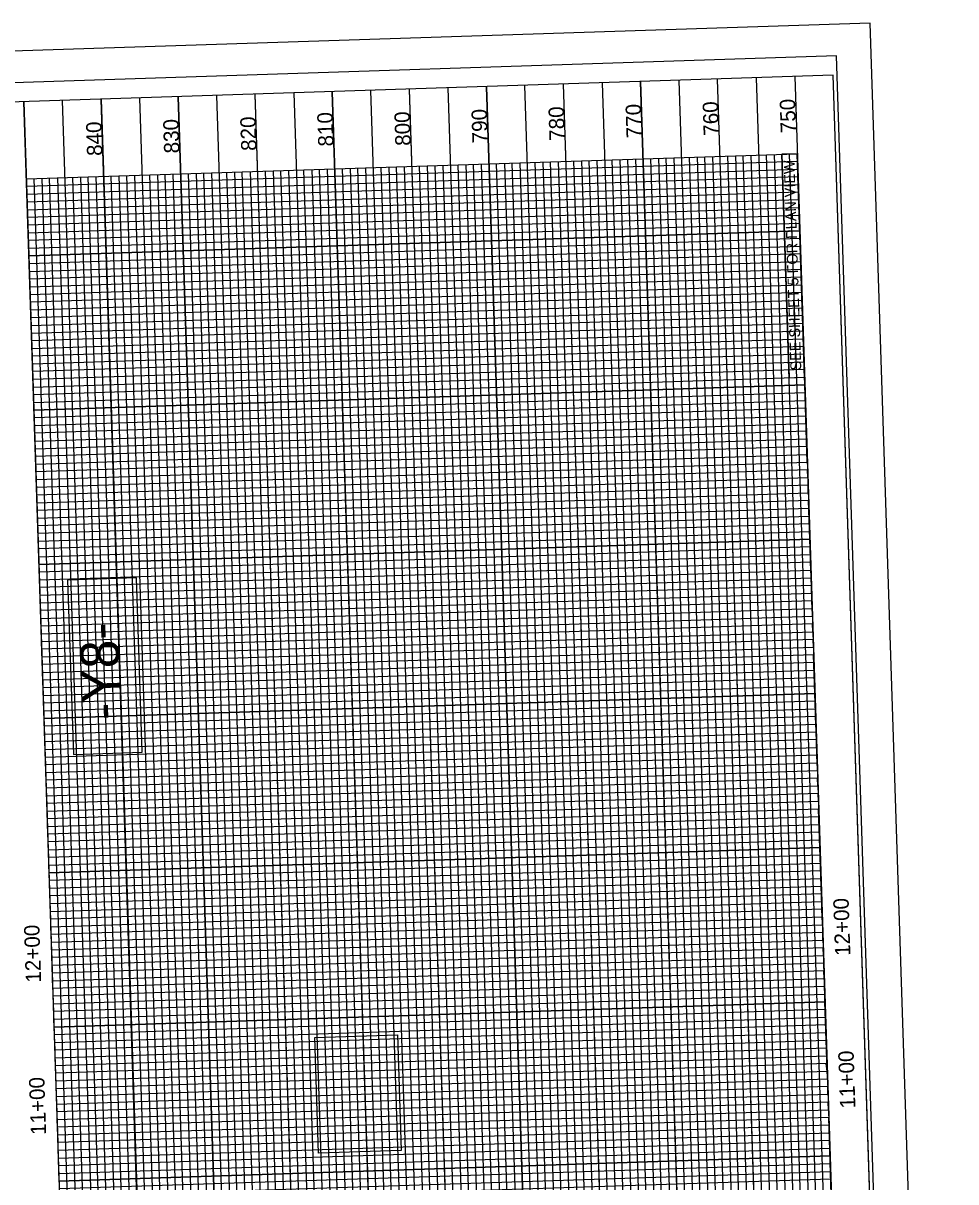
# Model space of a CAD drawing. Extents: x 1627314 to 1628469, y 762309 to 764247.
# Drawn here: x 1627864 to 1628469, y 763293 to 764044 of the extents above; entities that cross this region are included whole.
import ezdxf

# ---------------------------------------------------------------- set-up
doc = ezdxf.new("R2010")
doc.units = 0
for name, color, linetype in [('Exist Vertical Profile Horizontal Axis Label Major', 7, 'Continuous'), ('Exist Vertical Profile Vertical Axis Label', 7, 'Continuous'), ('Prop DSN Text', 7, 'Continuous'), ('Prop Grid Mask', 7, 'Continuous'), ('Sheet Data Field CELL', 7, 'Continuous'), ('Sheet DOT Grid CELL', 7, 'Continuous'), ('Sheet Layout Profile Border Port 2', 7, 'Continuous'), ('Sheet Plot Border Inside CELL', 7, 'Continuous'), ('Sheet Plot Border Outside CELL', 7, 'Continuous'), ('Sheet Profile CELL', 7, 'Continuous'), ('Sheet Profile Grid Major CELL', 7, 'Continuous'), ('Sheet Profile Grid Middle CELL', 7, 'Continuous'), ('Sheet Profile Grid Minor CELL', 7, 'Continuous')]:
    doc.layers.add(name, color=color, linetype=linetype)

msp = doc.modelspace()

# ---------------------------------------------------------------- linework, layer by layer
at = {"layer": 'Prop Grid Mask'}
for points in [[(1628356.37, 763959.45), (1628361.12, 763814.53), (1628371.11, 763814.85), (1628366.37, 763959.78)], [(1627941.73, 763571.76), (1627938.03, 763684.79), (1627893.31, 763683.33), (1627897.01, 763570.3)], [(1628055.96, 763312.01), (1628053.51, 763386.86), (1628107.11, 763388.61), (1628109.56, 763313.76)]]:
    msp.add_lwpolyline(points, close=True, dxfattribs=at)
at = {"layer": 'Sheet DOT Grid CELL'}
for p, q in [((1628313.83, 762507.28), (1628264.79, 764006.37)), ((1628363.8, 762508.92), (1628314.77, 764008)), ((1628063.96, 762499.11), (1628014.93, 763998.19)), ((1628113.93, 762500.74), (1628064.9, 763999.83)), ((1628163.91, 762502.38), (1628114.87, 764001.46)), ((1628213.88, 762504.01), (1628164.85, 764003.1)), ((1628263.85, 762505.65), (1628214.82, 764004.73)), ((1627914.04, 762494.2), (1627865.01, 763993.29)), ((1627964.01, 762495.84), (1627914.98, 763994.92)), ((1628013.99, 762497.47), (1627964.95, 763996.56)), ((1627866.64, 763943.43), (1628366.37, 763959.78)), ((1627868.27, 763893.46), (1628368, 763909.8)), ((1627869.91, 763843.48), (1628369.64, 763859.83)), ((1627871.54, 763793.51), (1628371.27, 763809.86)), ((1627873.18, 763743.54), (1628372.91, 763759.88)), ((1627874.81, 763693.56), (1628374.54, 763709.91)), ((1627876.44, 763643.59), (1628376.18, 763659.94)), ((1627878.08, 763593.62), (1628377.81, 763609.96)), ((1627879.71, 763543.64), (1628379.45, 763559.99)), ((1627881.35, 763493.67), (1628381.08, 763510.02)), ((1627882.98, 763443.7), (1628382.72, 763460.04)), ((1627884.62, 763393.72), (1628384.35, 763410.07)), ((1627886.25, 763343.75), (1628385.99, 763360.1)), ((1627887.89, 763293.78), (1628387.62, 763310.12))]:
    msp.add_line(p, q, dxfattribs=at)
at = {"layer": 'Sheet Layout Profile Border Port 2'}
msp.add_lwpolyline([(1627912.41, 762544.18), (1627866.64, 763943.43), (1628366.37, 763959.78), (1628412.14, 762560.52)], close=True, dxfattribs=at)
at = {"layer": 'Sheet Plot Border Inside CELL'}
msp.add_lwpolyline([(1628446.34, 762357.53), (1628391.86, 764023.14), (1627337.33, 763988.65), (1627391.81, 762323.04)], close=True, dxfattribs=at)
at = {"layer": 'Sheet Plot Border Outside CELL'}
msp.add_lwpolyline([(1628469.21, 762345.27), (1628413.63, 764044.37), (1627314.22, 764008.4), (1627369.79, 762309.31)], close=True, dxfattribs=at)
at = {"layer": 'Sheet Profile CELL'}
for p, q in [((1628364.74, 764009.75), (1628413.77, 762510.55)), ((1628438.76, 762511.37), (1628389.72, 764010.57)), ((1627914.04, 762494.2), (1627865, 763993.4))]:
    msp.add_line(p, q, dxfattribs=at)
msp.add_lwpolyline([(1627340.28, 763976.24), (1627389.32, 762477.04), (1628438.76, 762511.37), (1628389.72, 764010.57)], close=True, dxfattribs=at)
at = {"layer": 'Sheet Profile Grid Major CELL'}
for p, q in [((1627868.27, 763893.46), (1627866.64, 763943.43)), ((1628368, 763909.8), (1628368, 763909.8)), ((1627871.54, 763793.51), (1627869.91, 763843.48)), ((1627874.81, 763693.56), (1627873.18, 763743.54)), ((1627878.08, 763593.62), (1627876.44, 763643.59)), ((1627881.35, 763493.67), (1627879.71, 763543.64)), ((1627884.62, 763393.72), (1627882.98, 763443.7)), ((1627887.89, 763293.78), (1627886.25, 763343.75))]:
    msp.add_line(p, q, dxfattribs=at)
for points in [[(1628264.79, 764006.48), (1628313.83, 762507.28), (1628313.83, 762507.28), (1628363.8, 762508.92), (1628314.76, 764008.11)], [(1628364.74, 764009.75), (1628413.77, 762510.55)], [(1627964.95, 763996.67), (1628013.99, 762497.47), (1628063.96, 762499.11), (1628014.92, 763998.31)], [(1628064.9, 763999.94), (1628113.93, 762500.74), (1628163.91, 762502.38), (1628114.87, 764001.58)], [(1628164.84, 764003.21), (1628213.88, 762504.01), (1628263.85, 762505.65), (1628214.82, 764004.85)], [(1627914.98, 763995.04), (1627964.01, 762495.84)], [(1628389.25, 763260.15), (1628387.62, 763310.12), (1627887.89, 763293.78), (1627886.25, 763343.75), (1628385.99, 763360.1), (1628384.35, 763410.07), (1627884.62, 763393.72), (1627882.98, 763443.7), (1628382.72, 763460.04), (1628381.08, 763510.02), (1627881.35, 763493.67), (1627879.71, 763543.64), (1628379.45, 763559.99), (1628377.81, 763609.96), (1627878.08, 763593.62), (1627876.44, 763643.59), (1628376.18, 763659.94), (1628374.54, 763709.91), (1627874.81, 763693.56), (1627873.18, 763743.54), (1628372.91, 763759.88), (1628371.27, 763809.86), (1627871.54, 763793.51), (1627869.91, 763843.48), (1628369.64, 763859.83), (1628368, 763909.8), (1628368, 763909.8), (1627868.27, 763893.46), (1627866.64, 763943.43), (1628366.37, 763959.78)]]:
    msp.add_lwpolyline(points, dxfattribs=at)
at = {"layer": 'Sheet Profile Grid Middle CELL'}
for points in [[(1628239.8, 764005.66), (1628288.84, 762506.46), (1628338.81, 762508.1), (1628289.78, 764007.3)], [(1628339.75, 764008.93), (1628388.79, 762509.73)], [(1627939.96, 763995.85), (1627989, 762496.66), (1628038.97, 762498.29), (1627989.94, 763997.49)], [(1628039.91, 763999.12), (1628088.95, 762499.93), (1628138.92, 762501.56), (1628089.88, 764000.76)], [(1628139.86, 764002.39), (1628188.89, 762503.2), (1628238.87, 762504.83), (1628189.83, 764004.03)], [(1627939.03, 762495.02), (1627889.99, 763994.22)], [(1628388.44, 763285.14), (1628386.8, 763335.11), (1627887.07, 763318.76), (1627885.44, 763368.74), (1628385.17, 763385.08), (1628383.53, 763435.06), (1627883.8, 763418.71), (1627882.17, 763468.68), (1628381.9, 763485.03), (1628380.26, 763535), (1627880.53, 763518.66), (1627878.9, 763568.63), (1628378.63, 763584.98), (1628376.99, 763634.95), (1627877.26, 763618.6), (1627875.63, 763668.58), (1628375.36, 763684.92), (1628373.73, 763734.9), (1627873.99, 763718.55), (1627872.36, 763768.52), (1628372.09, 763784.87), (1628370.46, 763834.84), (1627870.72, 763818.5), (1627869.09, 763868.47), (1628368.82, 763884.82), (1628367.19, 763934.79), (1627867.45, 763918.44)]]:
    msp.add_lwpolyline(points, dxfattribs=at)
at = {"layer": 'Sheet Profile Grid Minor CELL'}
for p, q in [((1628192.26, 762553.33), (1628146.49, 763952.58)), ((1628151.48, 763952.75), (1628197.25, 762553.5)), ((1628202.25, 762553.66), (1628156.48, 763952.91)), ((1628161.48, 763953.07), (1628207.25, 762553.82)), ((1628217.24, 762554.15), (1628171.47, 763953.4)), ((1628176.47, 763953.56), (1628222.24, 762554.31)), ((1628227.24, 762554.48), (1628181.47, 763953.73)), ((1628186.47, 763953.89), (1628232.24, 762554.64)), ((1628242.23, 762554.97), (1628196.46, 763954.22)), ((1628201.46, 763954.38), (1628247.23, 762555.13)), ((1628252.22, 762555.29), (1628206.46, 763954.55)), ((1628211.45, 763954.71), (1628257.22, 762555.46)), ((1628267.22, 762555.78), (1628221.45, 763955.04)), ((1628226.44, 763955.2), (1628272.21, 762555.95)), ((1628277.21, 762556.11), (1628231.44, 763955.36)), ((1628236.44, 763955.53), (1628282.21, 762556.27)), ((1628292.2, 762556.6), (1628246.43, 763955.85)), ((1628251.43, 763956.02), (1628297.2, 762556.76)), ((1628302.2, 762556.93), (1628256.43, 763956.18)), ((1628261.43, 763956.34), (1628307.2, 762557.09)), ((1628317.19, 762557.42), (1628271.42, 763956.67)), ((1628276.42, 763956.83), (1628322.19, 762557.58)), ((1628327.18, 762557.75), (1628281.42, 763957)), ((1628286.41, 763957.16), (1628332.18, 762557.91)), ((1628342.18, 762558.24), (1628296.41, 763957.49)), ((1628301.4, 763957.65), (1628347.17, 762558.4)), ((1628352.17, 762558.56), (1628306.4, 763957.81)), ((1628311.4, 763957.98), (1628357.17, 762558.73)), ((1628367.16, 762559.05), (1628321.39, 763958.3)), ((1628326.39, 763958.47), (1628372.16, 762559.22)), ((1628377.16, 762559.38), (1628331.39, 763958.63)), ((1628336.39, 763958.8), (1628382.16, 762559.54)), ((1628392.15, 762559.87), (1628346.38, 763959.12)), ((1628351.38, 763959.29), (1628397.15, 762560.03)), ((1628402.14, 762560.2), (1628356.37, 763959.45)), ((1628361.37, 763959.61), (1628361.37, 763959.61)), ((1628407.14, 762560.36), (1628361.37, 763959.61)), ((1627911.61, 763944.9), (1627957.38, 762545.65)), ((1627967.38, 762545.98), (1627921.61, 763945.23)), ((1627926.6, 763945.39), (1627972.37, 762546.14)), ((1627977.37, 762546.3), (1627931.6, 763945.55)), ((1627936.6, 763945.72), (1627982.37, 762546.47)), ((1627992.36, 762546.79), (1627946.59, 763946.05)), ((1627951.59, 763946.21), (1627997.36, 762546.96)), ((1628002.36, 762547.12), (1627956.59, 763946.37)), ((1627961.59, 763946.54), (1628007.36, 762547.28)), ((1628017.35, 762547.61), (1627971.58, 763946.86)), ((1627976.58, 763947.03), (1628022.35, 762547.77)), ((1628027.34, 762547.94), (1627981.58, 763947.19)), ((1627986.57, 763947.35), (1628032.34, 762548.1)), ((1628042.34, 762548.43), (1627996.57, 763947.68)), ((1628001.56, 763947.84), (1628047.33, 762548.59)), ((1628052.33, 762548.75), (1628006.56, 763948.01)), ((1628011.56, 763948.17), (1628057.33, 762548.92)), ((1628067.32, 762549.25), (1628021.55, 763948.5)), ((1628026.55, 763948.66), (1628072.32, 762549.41)), ((1628077.32, 762549.57), (1628031.55, 763948.82)), ((1628036.55, 763948.99), (1628082.32, 762549.74)), ((1628092.31, 762550.06), (1628046.54, 763949.31)), ((1628051.54, 763949.48), (1628097.31, 762550.23)), ((1628102.3, 762550.39), (1628056.54, 763949.64)), ((1628061.53, 763949.8), (1628107.15, 762550.55)), ((1628117.3, 762550.88), (1628071.53, 763950.13)), ((1628076.52, 763950.3), (1628122.29, 762551.04)), ((1628127.29, 762551.21), (1628081.52, 763950.46)), ((1628086.52, 763950.62), (1628132.29, 762551.37)), ((1628142.28, 762551.7), (1628096.51, 763950.95)), ((1628101.51, 763951.11), (1628147.28, 762551.86)), ((1628152.28, 762552.02), (1628106.51, 763951.28)), ((1628111.51, 763951.44), (1628157.28, 762552.19)), ((1628167.27, 762552.51), (1628121.5, 763951.77)), ((1628126.5, 763951.93), (1628172.27, 762552.68)), ((1628177.26, 762552.84), (1628131.5, 763952.09)), ((1628136.49, 763952.26), (1628182.26, 762553)), ((1627917.4, 762544.34), (1627871.63, 763943.59)), ((1627876.63, 763943.76), (1627922.4, 762544.5)), ((1627927.4, 762544.67), (1627881.63, 763943.92)), ((1627886.63, 763944.08), (1627932.4, 762544.83)), ((1627942.39, 762545.16), (1627896.62, 763944.41)), ((1627901.62, 763944.57), (1627947.39, 762545.32)), ((1627952.38, 762545.49), (1627906.62, 763944.74))]:
    msp.add_line(p, q, dxfattribs=at)
for points in [[(1628374.87, 763699.91), (1628374.71, 763704.91), (1627874.97, 763688.57), (1627874.65, 763698.56), (1628374.38, 763714.91), (1628374.22, 763719.9), (1627874.48, 763703.56), (1627874.32, 763708.56), (1628374.05, 763724.9), (1628373.89, 763729.9), (1627874.16, 763713.55), (1627873.83, 763723.55), (1628373.56, 763739.89), (1628373.4, 763744.89), (1627873.67, 763728.54), (1627873.5, 763733.54), (1628373.24, 763749.89), (1628373.07, 763754.89), (1627873.34, 763738.54), (1627873.01, 763748.53), (1628372.74, 763764.88), (1628372.58, 763769.88), (1627872.85, 763753.53), (1627872.68, 763758.53), (1628372.42, 763774.87), (1628372.25, 763779.87), (1627872.52, 763763.53), (1627872.19, 763773.52), (1628371.93, 763789.87), (1628371.76, 763794.86), (1627872.03, 763778.52), (1627871.87, 763783.52), (1628371.6, 763799.86), (1628371.44, 763804.86), (1627871.7, 763788.51), (1627871.38, 763798.51), (1628371.11, 763814.85), (1628370.95, 763819.85), (1627871.21, 763803.5), (1627871.05, 763808.5), (1628370.78, 763824.85), (1628370.62, 763829.85), (1627870.89, 763813.5), (1627870.56, 763823.49), (1628370.29, 763839.84), (1628370.13, 763844.84), (1627870.4, 763828.49), (1627870.23, 763833.49), (1628369.97, 763849.83), (1628369.8, 763854.83), (1627870.07, 763838.49), (1627869.74, 763848.48), (1628369.48, 763864.83), (1628369.31, 763869.82), (1627869.58, 763853.48), (1627869.42, 763858.48), (1628369.15, 763874.82), (1628368.99, 763879.82), (1627869.25, 763863.47), (1627868.93, 763873.47), (1628368.66, 763889.81), (1628368.49, 763894.81), (1627868.76, 763878.46), (1627868.6, 763883.46), (1628368.33, 763899.81), (1628368.17, 763904.81), (1627868.43, 763888.46), (1627868.11, 763898.45), (1628367.84, 763914.8), (1628367.68, 763919.8), (1627867.94, 763903.45), (1627867.78, 763908.45), (1628367.51, 763924.79), (1628367.35, 763929.79), (1627867.62, 763913.45), (1627867.29, 763923.44), (1628367.02, 763939.79), (1628366.86, 763944.78), (1627867.13, 763928.44), (1627866.96, 763933.44), (1628366.7, 763949.78), (1628366.53, 763954.78), (1627866.8, 763938.43), (1627866.64, 763943.43)], [(1628384.84, 763395.08), (1627885.11, 763378.73), (1627884.94, 763383.73), (1628384.68, 763400.08), (1628384.51, 763405.07), (1627884.78, 763388.73), (1627884.45, 763398.72), (1628384.19, 763415.07), (1628384.02, 763420.06), (1627884.29, 763403.72), (1627884.13, 763408.72), (1628383.86, 763425.06), (1628383.7, 763430.06), (1627883.96, 763413.71), (1627883.64, 763423.71), (1628383.37, 763440.05), (1628383.21, 763445.05), (1627883.47, 763428.7), (1627883.31, 763433.7), (1628383.04, 763450.05), (1628382.88, 763455.05), (1627883.15, 763438.7), (1627882.82, 763448.69), (1628382.55, 763465.04), (1628382.39, 763470.04), (1627882.66, 763453.69), (1627882.49, 763458.69), (1628382.23, 763475.04), (1628382.06, 763480.03), (1627882.33, 763463.69), (1627882, 763473.68), (1628381.74, 763490.03), (1628381.57, 763495.02), (1627881.84, 763478.68), (1627881.68, 763483.68), (1628381.41, 763500.02), (1628381.24, 763505.02), (1627881.51, 763488.67), (1627881.19, 763498.67), (1628380.92, 763515.01), (1628380.75, 763520.01), (1627881.02, 763503.66), (1627880.86, 763508.66), (1628380.59, 763525.01), (1628380.43, 763530.01), (1627880.69, 763513.66), (1627880.37, 763523.65), (1628380.1, 763540), (1628379.94, 763545), (1627880.2, 763528.65), (1627880.04, 763533.65), (1628379.77, 763550), (1628379.61, 763554.99), (1627879.88, 763538.65), (1627879.55, 763548.64), (1628379.28, 763564.99), (1628379.12, 763569.98), (1627879.39, 763553.64), (1627879.22, 763558.64), (1628378.96, 763574.98), (1628378.79, 763579.98), (1627879.06, 763563.63), (1627878.73, 763573.63), (1628378.47, 763589.97), (1628378.3, 763594.97), (1627878.57, 763578.62), (1627878.41, 763583.62), (1628378.14, 763599.97), (1628377.98, 763604.97), (1627878.24, 763588.62), (1627877.92, 763598.61), (1628377.65, 763614.96), (1628377.49, 763619.96), (1627877.75, 763603.61), (1627877.59, 763608.61), (1628377.32, 763624.95), (1628377.16, 763629.95), (1627877.43, 763613.61), (1627877.1, 763623.6), (1628376.83, 763639.95), (1628376.67, 763644.94), (1627876.93, 763628.6), (1627876.77, 763633.6), (1628376.5, 763649.94), (1628376.34, 763654.94), (1627876.61, 763638.59), (1627876.28, 763648.59), (1628376.01, 763664.93), (1628375.85, 763669.93), (1627876.12, 763653.58), (1627875.95, 763658.58), (1628375.69, 763674.93), (1628375.52, 763679.93), (1627875.79, 763663.58), (1627875.46, 763673.57), (1628375.2, 763689.92), (1628375.03, 763694.92), (1627875.3, 763678.57), (1627875.14, 763683.57), (1628374.87, 763699.91)], [(1627888.21, 763283.78), (1628387.95, 763300.13), (1628387.78, 763305.13), (1627888.05, 763288.78), (1627887.72, 763298.77), (1628387.46, 763315.12), (1628387.29, 763320.12), (1627887.56, 763303.77), (1627887.4, 763308.77), (1628387.13, 763325.12), (1628386.97, 763330.11), (1627887.23, 763313.77), (1627886.91, 763323.76), (1628386.64, 763340.11), (1628386.48, 763345.1), (1627886.74, 763328.76), (1627886.58, 763333.76), (1628386.31, 763350.1), (1628386.15, 763355.1), (1627886.42, 763338.75), (1627886.09, 763348.75), (1628385.82, 763365.09), (1628385.12, 763369.77), (1628385.66, 763370.09), (1627885.93, 763353.75), (1627885.76, 763358.74), (1628385.49, 763375.09), (1628385.33, 763380.09), (1627885.6, 763363.74), (1627885.27, 763373.73), (1628385, 763390.08), (1628384.84, 763395.08)], [(1628388.27, 763290.13), (1628388.11, 763295.13), (1627888.38, 763278.79)]]:
    msp.add_lwpolyline(points, dxfattribs=at)

# ---------------------------------------------------------------- texts
at = {"layer": 'Exist Vertical Profile Horizontal Axis Label Major'}
for s, p in [('12+00', (1628400.88, 763439.94)), ('12+00', (1627876.17, 763422.63)), ('11+00', (1628404.12, 763341.07)), ('11+00', (1627879.4, 763323.91))]:
    msp.add_text(s, height=10, rotation=91.87347, dxfattribs=at).set_placement(p)
at = {"layer": 'Exist Vertical Profile Vertical Axis Label'}
for s, p in [('780', (1628215.76, 763968.29)), ('770', (1628265.73, 763969.92)), ('760', (1628315.71, 763971.56)), ('750', (1628365.68, 763973.19)), ('820', (1628015.87, 763961.75)), ('810', (1628065.8, 763964.58)), ('800', (1628115.81, 763965.02)), ('790', (1628165.79, 763966.65)), ('840', (1627915.92, 763958.48)), ('830', (1627965.89, 763960.12))]:
    msp.add_text(s, height=10, rotation=91.87347, dxfattribs=at).set_placement(p)
at = {"layer": 'Prop DSN Text'}
msp.add_text('SEE SHEET 5 FOR PLAN VIEW', height=7, rotation=91.87347, dxfattribs=at).set_placement((1628369.01, 763819.37))
at = {"layer": 'Sheet Data Field CELL'}
msp.add_text('-Y8-', height=25, rotation=91.87347, dxfattribs=at).set_placement((1627927.97, 763593.05))

doc.saveas('drawing.dxf')
